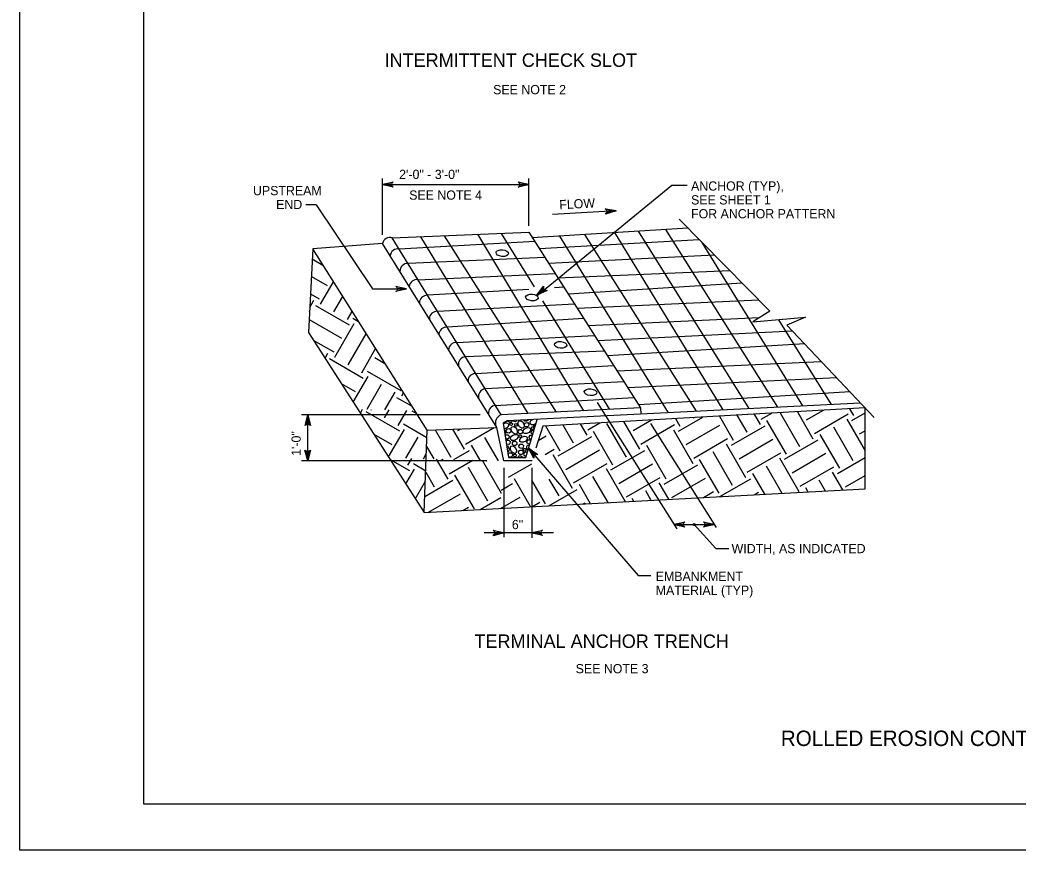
# Model space of a CAD drawing. Extents: x 636462 to 638208, y 299350 to 300538.
# Drawn here: x 636461.9 to 636785.5, y 299350.4 to 299619.7 of the extents above; entities that cross this region are included whole.
import ezdxf

# ---------------------------------------------------------------- set-up
doc = ezdxf.new("R2010")
doc.units = 0
for name, color, linetype in [('1', 7, 'Continuous'), ('Default', 7, 'Continuous'), ('PLT-BNDY', 7, 'Continuous')]:
    doc.layers.add(name, color=color, linetype=linetype)

msp = doc.modelspace()

# ---------------------------------------------------------------- linework, layer by layer
at = {"layer": '1'}
msp.add_lwpolyline([(637287.91, 299365.45), (637287.91, 299929.45), (636501.91, 299929.45), (636501.91, 299365.45), (637287.91, 299365.45), (637287.91, 299391.81), (637087.91, 299391.81), (637087.91, 299456.49), (637287.91, 299456.49), (637287.91, 299485.45), (637087.91, 299485.45), (637087.91, 299365.45), (637166.72, 299365.45), (637166.72, 299391.81), (637166.72, 299365.45), (637243.72, 299365.45), (637243.72, 299391.81), (637243.72, 299379.49), (637287.91, 299379.49)], dxfattribs=at)
at = {"layer": 'Default'}
for p, q in [((636579.43, 299550.05), (636579.43, 299568.29)), ((636626.92, 299553), (636626.92, 299568.29)), ((636629.43, 299530.28), (636673.27, 299566.15)), ((636673.27, 299566.15), (636678.17, 299566.15)), ((636557.93, 299559.75), (636554.64, 299559.75)), ((636557.93, 299559.75), (636576.18, 299532.5)), ((636678.47, 299552.23), (636627.82, 299549.06)), ((636582.6, 299549.06), (636626.92, 299550.87)), ((636617.87, 299491.63), (636582.6, 299549.06)), ((636591.72, 299549.43), (636626.55, 299492.06)), ((636635.82, 299492.53), (636599.5, 299549.75)), ((636610.2, 299550.19), (636644.61, 299492.96)), ((636628.68, 299533.14), (636617.98, 299550.5)), ((636626.92, 299550.87), (636663.09, 299493.89)), ((636636.79, 299549.62), (636672.06, 299492.31)), ((636681.27, 299492.78), (636645.08, 299550.14)), ((636654.65, 299550.74), (636689.72, 299493.21)), ((636698.27, 299493.64), (636662.47, 299551.23)), ((636671.17, 299551.77), (636707.49, 299494.11)), ((636628.8, 299547.91), (636584.87, 299545.37)), ((636630.29, 299545.56), (636682.14, 299548.51)), ((636715.67, 299494.52), (636683.04, 299547.59)), ((636632.11, 299542.69), (636587.72, 299540.73)), ((636687.09, 299543.48), (636633.37, 299540.7)), ((636556.66, 299542.21), (636560.12, 299540.21)), ((636556.38, 299536.55), (636561.47, 299533.61)), ((636590.94, 299535.48), (636635.39, 299537.52)), ((636636.29, 299536.11), (636692.04, 299538.46)), ((636559.34, 299527.56), (636563.53, 299534.81)), ((636638.26, 299533), (636635.15, 299532.81)), ((636696.08, 299534.36), (636639.69, 299530.75)), ((636556.09, 299530.89), (636558.95, 299529.24)), ((636563.71, 299525.04), (636566.57, 299529.99)), ((636576.18, 299532.5), (636576.18, 299532.5)), ((636576.18, 299532.5), (636587.25, 299532.5)), ((636626.85, 299532.33), (636594.05, 299530.41)), ((636555.87, 299526.42), (636557.23, 299528.78)), ((636557.74, 299527.14), (636568.66, 299520.83)), ((636597.25, 299525.21), (636641.67, 299527.64)), ((636653.19, 299493.39), (636631.44, 299528.67)), ((636642.57, 299526.22), (636701.4, 299528.96)), ((636568.07, 299522.52), (636569.61, 299525.17)), ((636569.8, 299522.98), (636571.68, 299521.89)), ((636701.59, 299523.1), (636646.23, 299520.46)), ((636555.67, 299522.51), (636566.14, 299516.46)), ((636563.95, 299510.34), (636570.26, 299521.25)), ((636644.69, 299522.87), (636600.43, 299520.03)), ((636707.81, 299522.5), (636724.85, 299494.98)), ((636568.32, 299507.82), (636574.17, 299517.94)), ((636603.48, 299515.06), (636648.22, 299517.32)), ((636649.24, 299515.72), (636712.35, 299518.86)), ((636557.01, 299515.91), (636563.62, 299512.1)), ((636716.31, 299514.65), (636652.4, 299510.74)), ((636560.83, 299509.97), (636561.77, 299511.6)), ((636572.69, 299505.3), (636577.21, 299513.12)), ((636576.98, 299510.21), (636580.23, 299508.33)), ((636651.39, 299512.32), (636606.3, 299510.47)), ((636562.23, 299509.88), (636573.15, 299503.57)), ((636609.65, 299505.01), (636654.37, 299507.63)), ((636655.47, 299505.9), (636721.67, 299508.97)), ((636569.98, 299495.74), (636574.8, 299504.08)), ((636574.46, 299505.84), (636585.38, 299499.53)), ((636726.7, 299503.64), (636658.95, 299500.42)), ((636566.06, 299501.84), (636570.63, 299499.2)), ((636574.48, 299493.44), (636579.16, 299501.56)), ((636657.76, 299502.29), (636612.7, 299500.05)), ((636580.19, 299493.25), (636583.53, 299499.03)), ((636583.99, 299497.31), (636589.01, 299494.42)), ((636585.71, 299497.77), (636586.28, 299498.75)), ((636615.99, 299494.69), (636660.92, 299497.31)), ((636731.03, 299499.06), (636662.49, 299494.85)), ((636663.09, 299493.89), (636617.87, 299491.63)), ((636648.99, 299495.63), (636674.87, 299454.61)), ((636663.09, 299493.89), (636663.2, 299491.86)), ((636611.05, 299491.63), (636553.13, 299491.63)), ((636572.27, 299492.19), (636573.01, 299493.49)), ((636574.03, 299492.72), (636584.94, 299486.42)), ((636575.75, 299493.18), (636575.87, 299493.4)), ((636580.11, 299490.66), (636581.59, 299493.21)), ((636584.48, 299488.14), (636587.3, 299493.02)), ((636588.91, 299492.97), (636590.5, 299492.06)), ((636675.35, 299486.36), (636683.25, 299490.93)), ((636680.1, 299490.75), (636680.22, 299490.53)), ((636688.66, 299491.23), (636693.16, 299483.44)), ((636694.3, 299491.55), (636697.53, 299485.96)), ((636699.94, 299491.87), (636701.9, 299488.48)), ((636702.23, 299490.24), (636705.61, 299492.18)), ((636708.32, 299492.29), (636714.62, 299481.38)), ((636713.94, 299492.65), (636718.99, 299483.9)), ((636716.93, 299489.99), (636722.37, 299493.13)), ((636719.45, 299485.62), (636730.37, 299491.93)), ((636730.86, 299493.6), (636732.09, 299491.46)), ((636731.59, 299489.82), (636735.9, 299492.31)), ((636586.25, 299488.68), (636593.82, 299484.31)), ((636606.39, 299482.17), (636615.66, 299487.52)), ((636632.26, 299488.06), (636636.92, 299479.99)), ((636637.91, 299488.37), (636641.29, 299482.51)), ((636643.55, 299488.69), (636645.66, 299485.03)), ((636645.99, 299486.78), (636649.92, 299489.05)), ((636652.08, 299488.84), (636658.39, 299477.92)), ((636657.54, 299489.48), (636662.76, 299480.45)), ((636660.69, 299486.54), (636666.68, 299489.99)), ((636663.22, 299482.17), (636674.13, 299488.47)), ((636666.28, 299488.84), (636687.58, 299455.09)), ((636674.46, 299490.43), (636675.86, 299488.01)), ((636677.87, 299482), (636688.79, 299488.3)), ((636692.57, 299481.75), (636703.49, 299488.05)), ((636703.95, 299489.77), (636710.26, 299478.86)), ((636725.62, 299487.73), (636731.93, 299476.81)), ((636729.99, 299490.25), (636735.9, 299480.01)), ((636576.65, 299485.38), (636582.42, 299482.05)), ((636581.42, 299477.97), (636586.59, 299486.92)), ((636587.01, 299477.56), (636590.96, 299484.4)), ((636596.46, 299486.76), (636601.56, 299477.92)), ((636602.15, 299486.98), (636605.93, 299480.45)), ((636603.87, 299486.54), (636604.83, 299487.09)), ((636612.56, 299484.27), (636616.9, 299476.75)), ((636629.94, 299483.34), (636632.55, 299484.85)), ((636636.34, 299478.29), (636647.25, 299484.6)), ((636647.72, 299486.32), (636654.02, 299475.4)), ((636673.75, 299486.8), (636680.06, 299475.88)), ((636721.26, 299485.21), (636727.56, 299474.29)), ((636734.11, 299485.45), (636735.9, 299486.49)), ((636593.73, 299481.41), (636596.09, 299477.32)), ((636608.19, 299481.75), (636610.98, 299476.92)), ((636665.02, 299481.75), (636671.32, 299470.83)), ((636680.39, 299477.63), (636691.31, 299483.93)), ((636690.85, 299482.21), (636697.16, 299471.29)), ((636695.09, 299477.38), (636706.01, 299483.69)), ((636709.75, 299477.21), (636720.67, 299483.51)), ((636592.74, 299477.41), (636593.64, 299478.97)), ((636602.55, 299477.14), (636607.61, 299480.06)), ((636626.75, 299480.79), (636662.34, 299439.48)), ((636632.15, 299478.79), (636635.08, 299480.48)), ((636634.62, 299478.76), (636640.92, 299467.84)), ((636638.86, 299473.93), (636649.78, 299480.23)), ((636653.51, 299473.76), (636664.43, 299480.06)), ((636686.48, 299479.69), (636692.79, 299468.77)), ((636697.62, 299473.01), (636708.53, 299479.32)), ((636712.27, 299472.84), (636723.19, 299479.15)), ((636726.97, 299472.6), (636735.9, 299477.75)), ((636613.25, 299476.7), (636553.13, 299476.7)), ((636581.96, 299477.13), (636588.16, 299473.55)), ((636587.7, 299475.27), (636588.99, 299477.51)), ((636589.47, 299475.81), (636593.46, 299473.51)), ((636596.81, 299477.3), (636600.57, 299470.8)), ((636598.51, 299476.89), (636599.11, 299477.24)), ((636601.03, 299472.52), (636608.75, 299476.98)), ((636607.2, 299474.62), (636613.5, 299463.71)), ((636611.71, 299476.9), (636617.87, 299466.23)), ((636613.16, 299476.71), (636613.4, 299476.85)), ((636618.78, 299474.44), (636618.78, 299451.9)), ((636620.33, 299471.45), (636627.81, 299475.77)), ((636627.82, 299474.44), (636627.82, 299451.77)), ((636641.38, 299469.56), (636652.3, 299475.86)), ((636656.04, 299469.39), (636666.96, 299475.69)), ((636670.74, 299469.14), (636681.65, 299475.44)), ((636682.12, 299477.17), (636688.42, 299466.25)), ((636703.79, 299475.12), (636708.93, 299466.21)), ((636708.16, 299477.64), (636714.46, 299466.72)), ((636714.79, 299468.47), (636725.71, 299474.78)), ((636587.03, 299469.25), (636589.81, 299474.06)), ((636593.44, 299473.05), (636596.2, 299468.27)), ((636602.83, 299472.1), (636609.13, 299461.18)), ((636647.55, 299471.67), (636652.46, 299463.17)), ((636651.92, 299474.19), (636658.1, 299463.47)), ((636658.56, 299465.02), (636669.48, 299471.32)), ((636699.42, 299472.6), (636703.28, 299465.9)), ((636725.25, 299473.06), (636728.6, 299467.27)), ((636729.5, 299468.23), (636735.9, 299471.93)), ((636590.1, 299464.48), (636593.34, 299470.09)), ((636593.18, 299465.18), (636602.24, 299470.41)), ((636617.91, 299467.24), (636621.54, 299469.34)), ((636622.13, 299471.03), (636627.44, 299461.82)), ((636627.75, 299470.47), (636632.18, 299462.79)), ((636633.38, 299470.81), (636636.55, 299465.32)), ((636643.18, 299469.15), (636646.81, 299462.87)), ((636669.02, 299469.6), (636672.12, 299464.23)), ((636673.26, 299464.77), (636684.18, 299471.08)), ((636688.82, 299465.13), (636698.83, 299470.91)), ((636716.52, 299468.01), (636717.3, 299466.66)), ((636720.88, 299470.53), (636722.95, 299466.96)), ((636594.38, 299460.05), (636604.77, 299466.04)), ((636611.06, 299460.94), (636617.82, 299464.84)), ((636617.71, 299461.3), (636624.07, 299464.97)), ((636633.4, 299462.15), (636642.6, 299467.45)), ((636664.65, 299467.08), (636666.47, 299463.92)), ((636683.45, 299464.84), (636686.7, 299466.71)), ((636686.32, 299465.04), (636686.34, 299464.99)), ((636699.95, 299465.73), (636701.36, 299466.54)), ((636605.5, 299460.64), (636607.29, 299461.67)), ((636628.04, 299461.86), (636630.46, 299463.26)), ((636644.53, 299462.74), (636645.12, 299463.08)), ((636660.28, 299464.56), (636660.82, 299463.62)), ((636673.97, 299456.03), (636686.98, 299456.03)), ((636680.47, 299456.03), (636687.55, 299448.31)), ((636687.55, 299448.31), (636691.67, 299448.31)), ((636662.34, 299439.48), (636666.46, 299439.48))]:
    msp.add_line(p, q, dxfattribs=at)
for points in [[(636582.66, 299565.69), (636582.93, 299565.47), (636579.43, 299566.33), (636582.66, 299565.69), (636582.47, 299566.07), (636579.43, 299566.33), (636582.46, 299566.59), (636582.64, 299566.97), (636579.43, 299566.33), (636582.93, 299567.22), (636582.64, 299566.97)], [(636579.43, 299566.33), (636626.92, 299566.33)], [(636623.68, 299566.97), (636623.42, 299567.19), (636626.92, 299566.33), (636623.68, 299566.97), (636623.88, 299566.6), (636626.92, 299566.33), (636623.89, 299566.07), (636623.7, 299565.7), (636626.92, 299566.33), (636623.42, 299565.44), (636623.7, 299565.7)], [(636655.16, 299557.86), (636634.57, 299556.65)], [(636651.89, 299558.3), (636651.61, 299558.51), (636655.16, 299557.86), (636651.89, 299558.3), (636652.11, 299557.94), (636655.16, 299557.86), (636652.15, 299557.42), (636651.99, 299557.03), (636655.16, 299557.86), (636651.72, 299556.76), (636651.99, 299557.03)], [(636675.6, 299555.14), (636705.02, 299525.28), (636699.48, 299521.76), (636716.6, 299523.27), (636710.56, 299520.75), (636738.85, 299490.77)], [(636593.9, 299486.65), (636616.52, 299487.56), (636579.43, 299547.25), (636556.82, 299545.44)], [(636584.02, 299533.14), (636583.75, 299533.36), (636587.25, 299532.5), (636584.02, 299533.14), (636584.22, 299532.77), (636587.25, 299532.5), (636584.22, 299532.24), (636584.04, 299531.87), (636587.25, 299532.5), (636583.76, 299531.62), (636584.04, 299531.87)], [(636632.42, 299532.02), (636632.77, 299532.02), (636629.52, 299530.46), (636632.42, 299532.02), (636632.03, 299532.18), (636629.52, 299530.46), (636631.69, 299532.58), (636631.59, 299532.99), (636629.52, 299530.46), (636631.65, 299533.37), (636631.59, 299532.99)], [(636593, 299459.97), (636735.9, 299467.66), (636735.9, 299493.89), (636631.44, 299488.01), (636629.14, 299480.83)], [(636734.35, 299495.46), (636619.82, 299489.67), (636618.56, 299488.91), (636620.32, 299477.84), (636625.86, 299477.84), (636629.6, 299490.16)], [(636554.55, 299488.4), (636554.33, 299488.13), (636555.19, 299491.63), (636554.55, 299488.4), (636554.92, 299488.59), (636555.19, 299491.63), (636555.45, 299488.6), (636555.82, 299488.42), (636555.19, 299491.63), (636556.07, 299488.13), (636555.82, 299488.42)], [(636555.19, 299476.7), (636555.19, 299491.63)], [(636627.85, 299476.8), (636627.82, 299476.7), (636618.78, 299476.7), (636616.52, 299487.56)], [(636618.59, 299488.73), (636619.29, 299489), (636619.97, 299488.94), (636620.3, 299488.64), (636620.29, 299488.08), (636619.79, 299487.45), (636619.03, 299487.07), (636618.86, 299487.07)], [(636619.87, 299489.67), (636619.87, 299489.59), (636619.47, 299489.27), (636619.18, 299489.29)], [(636621.52, 299489.75), (636621.5, 299489.57), (636621.11, 299489.24), (636620.48, 299489.29), (636620.19, 299489.57), (636620.16, 299489.69)], [(636620.67, 299488.7), (636620.91, 299489.04), (636621.29, 299489.06), (636621.55, 299488.78), (636621.51, 299488.4), (636621.28, 299488.2), (636620.9, 299488.23), (636620.73, 299488.4), (636620.67, 299488.7)], [(636622.83, 299487.16), (636623.13, 299486.42), (636623.07, 299485.73), (636622.76, 299485.41), (636622.21, 299485.42), (636621.58, 299485.91), (636621.2, 299486.67), (636621.18, 299487.39), (636621.47, 299487.79), (636622.04, 299487.83), (636622.55, 299487.5), (636622.85, 299487.13)], [(636622.76, 299489.82), (636622.74, 299489.59), (636622.51, 299489.4), (636622.13, 299489.42), (636621.96, 299489.59), (636621.92, 299489.78)], [(636622.23, 299488.42), (636622.47, 299488.76), (636622.85, 299488.78), (636623.12, 299488.51), (636623.08, 299488.12), (636622.84, 299487.93), (636622.47, 299487.95), (636622.29, 299488.12), (636622.23, 299488.42)], [(636625.08, 299489.03), (636625.37, 299488.29), (636625.31, 299487.61), (636625.01, 299487.28), (636624.45, 299487.29), (636623.82, 299487.79), (636623.44, 299488.55), (636623.43, 299489.26), (636623.72, 299489.67), (636624.29, 299489.7), (636624.8, 299489.38), (636625.1, 299489)], [(636625.69, 299487.2), (636626.44, 299487.49), (636627.12, 299487.43), (636627.44, 299487.12), (636627.43, 299486.57), (636626.94, 299485.94), (636626.18, 299485.56), (636625.46, 299485.55), (636625.06, 299485.83), (636625.02, 299486.41), (636625.35, 299486.92), (636625.72, 299487.22)], [(636626.66, 299490.01), (636626.65, 299489.87), (636626.26, 299489.55), (636625.63, 299489.59), (636625.34, 299489.88), (636625.32, 299489.95)], [(636625.42, 299488.51), (636625.81, 299489.07), (636626.45, 299489.11), (636626.89, 299488.65), (636626.82, 299488.01), (636626.43, 299487.69), (636625.81, 299487.73), (636625.51, 299488.02), (636625.42, 299488.51)], [(636629.18, 299488.79), (636629.18, 299488.78), (636628.41, 299488.4), (636627.7, 299488.39), (636627.29, 299488.67), (636627.26, 299489.25), (636627.58, 299489.76), (636627.96, 299490.06)], [(636627.64, 299487.36), (636627.88, 299487.7), (636628.26, 299487.72), (636628.53, 299487.44), (636628.49, 299487.06), (636628.25, 299486.86), (636627.88, 299486.89), (636627.7, 299487.06), (636627.64, 299487.36)], [(636627.93, 299490.04), (636628.05, 299490.09)], [(636628.46, 299488.05), (636628.7, 299488.39), (636629.07, 299488.41)], [(636628.81, 299487.57), (636628.7, 299487.58), (636628.52, 299487.75), (636628.46, 299488.05)], [(636629.47, 299490.16), (636629.57, 299490.07)], [(636618.91, 299486.73), (636619.01, 299486.74), (636619.45, 299486.28), (636619.39, 299485.64), (636619.12, 299485.42)], [(636619.21, 299484.86), (636619.39, 299485.11), (636620.02, 299485.15), (636620.46, 299484.69), (636620.4, 299484.05), (636620.01, 299483.73), (636619.38, 299483.77), (636619.38, 299483.77)], [(636619.52, 299486.55), (636619.92, 299487.12), (636620.55, 299487.16), (636620.99, 299486.7), (636620.93, 299486.06), (636620.54, 299485.73), (636619.91, 299485.78), (636619.62, 299486.06), (636619.52, 299486.55)], [(636621.66, 299485), (636622.4, 299485.29), (636623.08, 299485.24), (636623.4, 299484.93), (636623.39, 299484.37), (636622.9, 299483.74), (636622.14, 299483.36), (636621.42, 299483.35), (636621.02, 299483.64), (636620.98, 299484.21), (636621.31, 299484.72), (636621.69, 299485.02)], [(636623.4, 299486.33), (636623.8, 299486.89), (636624.44, 299486.93), (636624.88, 299486.47), (636624.81, 299485.83), (636624.42, 299485.5), (636623.79, 299485.55), (636623.5, 299485.83), (636623.41, 299486.33)], [(636623.59, 299484.83), (636623.82, 299485.16), (636624.2, 299485.19), (636624.47, 299484.91), (636624.43, 299484.53), (636624.2, 299484.33), (636623.82, 299484.36), (636623.64, 299484.53), (636623.59, 299484.83)], [(636624.61, 299484.39), (636625.36, 299484.68), (636626.04, 299484.63), (636626.36, 299484.32), (636626.35, 299483.76), (636625.86, 299483.13), (636625.1, 299482.75), (636624.38, 299482.74), (636623.98, 299483.03), (636623.94, 299483.6), (636624.27, 299484.11), (636624.64, 299484.41)], [(636626.97, 299484.46), (636627.36, 299485.03), (636628, 299485.06), (636628.04, 299485.02)], [(636627.63, 299483.67), (636627.36, 299483.69), (636627.06, 299483.97), (636626.97, 299484.46)], [(636627.62, 299486.12), (636628.01, 299486.68), (636628.55, 299486.71)], [(636628.13, 299485.33), (636628.01, 299485.34), (636627.71, 299485.63), (636627.62, 299486.12)], [(636619.5, 299483.04), (636619.76, 299483.42), (636620.4, 299483.46), (636620.84, 299483), (636620.77, 299482.36), (636620.38, 299482.04), (636619.76, 299482.08), (636619.63, 299482.2)], [(636619.71, 299481.72), (636619.91, 299481.59), (636620.21, 299481.22)], [(636620.19, 299481.25), (636620.49, 299480.51), (636620.43, 299479.82), (636620.12, 299479.5), (636620.06, 299479.5)], [(636622.54, 299480.89), (636622.84, 299480.15), (636622.78, 299479.46), (636622.47, 299479.14), (636621.92, 299479.15), (636621.29, 299479.64), (636620.91, 299480.4), (636620.9, 299481.12), (636621.18, 299481.52), (636621.75, 299481.56), (636622.26, 299481.23), (636622.56, 299480.86)], [(636621.54, 299482.51), (636621.93, 299483.08), (636622.57, 299483.11), (636623.01, 299482.66), (636622.94, 299482.02), (636622.55, 299481.69), (636621.93, 299481.74), (636621.63, 299482.02), (636621.54, 299482.51)], [(636623.67, 299481.55), (636624.07, 299482.12), (636624.7, 299482.15), (636625.15, 299481.7), (636625.08, 299481.05), (636624.69, 299480.73), (636624.06, 299480.77), (636623.77, 299481.06), (636623.67, 299481.55)], [(636626.53, 299480.03), (636626.21, 299480.67), (636626.19, 299481.38), (636626.48, 299481.79), (636627.05, 299481.82), (636627.07, 299481.81)], [(636626.22, 299482.97), (636626.62, 299483.53), (636627.25, 299483.57), (636627.52, 299483.29)], [(636627.17, 299482.15), (636626.61, 299482.19), (636626.32, 299482.48), (636626.22, 299482.97)], [(636555.82, 299479.94), (636556.05, 299480.21), (636555.19, 299476.7), (636555.82, 299479.94), (636555.45, 299479.74), (636555.19, 299476.7), (636554.93, 299479.73), (636554.55, 299479.92), (636555.19, 299476.7), (636554.3, 299480.2), (636554.55, 299479.92)], [(636620.17, 299478.83), (636620.49, 299479.29), (636621.12, 299479.33), (636621.56, 299478.87), (636621.5, 299478.23), (636621.11, 299477.9), (636620.48, 299477.95), (636620.27, 299478.15)], [(636621.9, 299478.55), (636622.14, 299478.89), (636622.52, 299478.91), (636622.78, 299478.64), (636622.74, 299478.25), (636622.51, 299478.06), (636622.13, 299478.08), (636621.96, 299478.26), (636621.9, 299478.55)], [(636623.43, 299477.84), (636623.43, 299477.92), (636623.72, 299478.33), (636624.29, 299478.37), (636624.8, 299478.04), (636624.96, 299477.84)], [(636623.56, 299479.59), (636623.96, 299480.15), (636624.59, 299480.19), (636625.03, 299479.73), (636624.97, 299479.09), (636624.58, 299478.77), (636623.95, 299478.81), (636623.66, 299479.1), (636623.56, 299479.59)], [(636625.04, 299480.39), (636625.28, 299480.73), (636625.66, 299480.75), (636625.92, 299480.48), (636625.88, 299480.1), (636625.65, 299479.9), (636625.27, 299479.93), (636625.1, 299480.1), (636625.04, 299480.39)], [(636625.24, 299479.03), (636625.64, 299479.59), (636626.27, 299479.63), (636626.37, 299479.52)], [(636625.98, 299478.23), (636625.63, 299478.25), (636625.34, 299478.54), (636625.24, 299479.03)], [(636628.49, 299477.97), (636628.51, 299477.62), (636626.76, 299480.77), (636628.49, 299477.97), (636628.63, 299478.37), (636626.76, 299480.77), (636629.01, 299478.73), (636629.41, 299478.85), (636626.76, 299480.77), (636629.78, 299478.82), (636629.41, 299478.85)], [(636677.2, 299455.4), (636677.47, 299455.17), (636673.97, 299456.03), (636677.2, 299455.4), (636677.01, 299455.77), (636673.97, 299456.03), (636677, 299456.29), (636677.18, 299456.67), (636673.97, 299456.03), (636677.46, 299456.92), (636677.18, 299456.67)], [(636683.75, 299456.67), (636683.48, 299456.89), (636686.98, 299456.03), (636683.75, 299456.67), (636683.94, 299456.3), (636686.98, 299456.03), (636683.95, 299455.78), (636683.77, 299455.4), (636686.98, 299456.03), (636683.48, 299455.15), (636683.77, 299455.4)], [(636618.78, 299453.32), (636612.43, 299453.32)], [(636615.54, 299453.96), (636615.28, 299454.18), (636618.78, 299453.32), (636615.54, 299453.96), (636615.74, 299453.59), (636618.78, 299453.32), (636615.75, 299453.06), (636615.56, 299452.69), (636618.78, 299453.32), (636615.28, 299452.43), (636615.56, 299452.69)], [(636634.9, 299453.32), (636618.78, 299453.32)], [(636631.05, 299452.68), (636631.32, 299452.46), (636627.82, 299453.32), (636631.05, 299452.68), (636630.86, 299453.06), (636627.82, 299453.32), (636630.85, 299453.58), (636631.03, 299453.96), (636627.82, 299453.32), (636631.32, 299454.21), (636631.03, 299453.96)]]:
    msp.add_lwpolyline(points, dxfattribs=at)
msp.add_lwpolyline([(636556.82, 299545.44), (636555.46, 299518.31), (636593, 299459.97), (636593.9, 299486.65)], close=True, dxfattribs=at)
msp.add_circle((636680.47, 299456.03), 0.343, dxfattribs=at)
for centre, radius, start, end in [((636581.86, 299546.68), 2.49, 72.7069, 166.7829), ((636584.31, 299543.1), 2.34, 76.3134, 178.5059), ((636587.58, 299538.22), 2.51, 86.881, 180.957), ((636590.56, 299533.07), 2.45, 81.0848, 175.1608), ((636593.86, 299527.96), 2.46, 85.5141, 179.5901), ((636597.07, 299522.78), 2.44, 85.7547, 179.8307), ((636600.14, 299517.65), 2.4, 83.1666, 177.2427), ((636603.26, 299512.68), 2.39, 84.6038, 178.6799), ((636606.53, 299508), 2.49, 95.3824, 189.4584), ((636609.54, 299502.65), 2.37, 87.2651, 181.3412), ((636613.02, 299497.59), 2.48, 97.5379, 191.6139), ((636616.19, 299492.29), 2.41, 94.6317, 188.7077), ((636618.83, 299489.03), 2.77, 110.1867, 204.2627)]:
    msp.add_arc(centre, radius, start, end, dxfattribs=at)
for centre in [(636618.26, 299544.1), (636627.86, 299529.7), (636637.18, 299514.34), (636646.88, 299498.97)]:
    msp.add_ellipse(centre, major_axis=(-2.01, 0.18), ratio=0.535303, dxfattribs=at)
at = {"layer": 'PLT-BNDY'}
msp.add_lwpolyline([(636461.91, 299944.45), (637302.91, 299944.45), (637302.91, 299350.45), (636461.91, 299350.45)], close=True, dxfattribs=at)

# ---------------------------------------------------------------- texts
at = {"layer": 'Default'}
for s, height, p in [('INTERMITTENT CHECK SLOT', 4.3721, (636580.11, 299604.52)), ('SEE NOTE 2', 2.998, (636615.31, 299595.64)), ('2\'-0" - 3\'-0"', 2.998, (636584.85, 299568.15)), ('UPSTREAM ', 2.998, (636537.46, 299562.88)), ('ANCHOR (TYP),', 2.998, (636679.47, 299564.36)), ('SEE NOTE 4', 2.998, (636588.09, 299561.42)), ('SEE SHEET 1', 2.998, (636679.47, 299559.87)), ('END', 2.998, (636544.96, 299558.38)), ('FOR ANCHOR PATTERN', 2.998, (636679.47, 299555.37)), ('6"', 2.998, (636621.38, 299454.55)), ('WIDTH, AS INDICATED', 2.998, (636692.61, 299446.75)), ('EMBANKMENT ', 2.998, (636668.01, 299437.72)), ('MATERIAL (TYP)', 2.998, (636668.01, 299433.22)), ('TERMINAL ANCHOR TRENCH', 4.3721, (636609.25, 299416.01)), ('SEE NOTE 3', 2.998, (636642.06, 299407.79)), ('ROLLED EROSION CONTROL PRODUCTS (RECP)', 4.9967, (636708.57, 299384.2))]:
    msp.add_text(s, height=height, dxfattribs=at).set_placement(p)
for s, rotation, p in [('FLOW', 2.8825, (636636.83, 299558.3)), ('1\'-0"', 90, (636552.94, 299478.33))]:
    msp.add_text(s, height=2.998, rotation=rotation, dxfattribs=at).set_placement(p)

doc.saveas('drawing.dxf')
